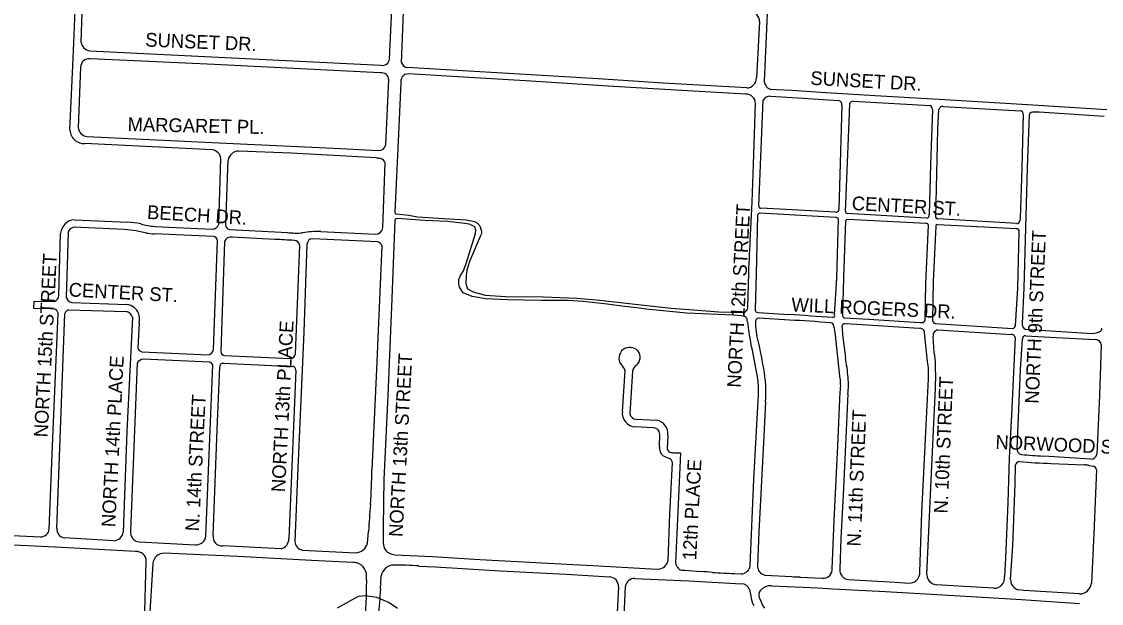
# Model space of a CAD drawing. Extents: x 0 to 712119, y 0 to 761125.
# Drawn here: x 682403 to 686331, y 737468 to 739583 of the extents above; entities that cross this region are included whole.
import ezdxf

# ---------------------------------------------------------------- set-up
doc = ezdxf.new("R2010")
doc.units = 0
for name, color, linetype in [('PAVED ROADS', 7, 'Continuous'), ('stream or creek', 7, 'Continuous'), ('street names', 7, 'Continuous')]:
    doc.layers.add(name, color=color, linetype=linetype)

msp = doc.modelspace()

# ---------------------------------------------------------------- linework, layer by layer
at = {"layer": 'PAVED ROADS'}
for points in [[(685104.8, 739365.5), (685126.5, 739832.4), (685138.5, 740091.5)], [(682578.5, 739189), (682590, 739449.5), (682599.5, 739683), (682609.6, 739931.8), (682635.8, 739930.4), (682631.1, 739819.2)], [(683785, 739433), (683793.5, 739649.5), (683799.8, 739773.9)], [(682626, 739724.5), (682618.7, 739510.1)], [(683741.5, 739447), (683751.5, 739682)], [(685087.6, 739583.4), (685076.4, 739378.9)], [(682650.6, 739476.9), (683710, 739424.5)], [(682616.5, 739417.5), (682608, 739198)], [(683707.5, 739397), (683417.8, 739411.3), (683104.5, 739427.5), (682652.5, 739448.5)], [(685040.6, 739342.1), (684737, 739359.5), (684500.5, 739375), (684255.5, 739390), (684029, 739403), (683805.5, 739416)], [(685038, 739319.5), (684846, 739330), (684556, 739347.5), (684236.5, 739367.5), (683929, 739386), (683811.5, 739393)], [(683728, 739136), (683739, 739372)], [(683782, 739361.5), (683774.5, 739173.5), (683761, 738890.5)], [(685127, 739312), (685246.5, 739305.5), (685375, 739297)], [(686351, 739262.5), (686062, 739281.2), (685760, 739299), (685507.5, 739313.5), (685328.5, 739324.5), (685204.5, 739332.5), (685150.3, 739335.5), (685131.1, 739336.7)], [(685060, 738928.5), (685065, 739063.5), (685072.5, 739286)], [(685085, 738913), (685100.5, 739297.5)], [(685386.5, 739278.5), (685376, 738901)], [(685400.5, 738892.5), (685413.5, 739220), (685416, 739286.5)], [(685427.5, 739293.5), (685707.5, 739278.5)], [(685716, 739264), (685709.5, 739062.5), (685704.5, 738882)], [(685728.5, 738871.5), (685736.2, 739191.3), (685739.3, 739264.4)], [(685755, 739275), (686037, 739259)], [(686046, 739248.5), (686041, 739050.5), (686035, 738868.5), (686034.5, 738859), (686034.5, 738859)], [(686068, 739244), (686061.3, 739051.8), (686048.5, 738613.5), (686043, 738486)], [(686341, 739238.5), (686104.8, 739254.4), (686086.5, 739254.5)], [(682640, 739165.5), (683147, 739141.5), (683563, 739121.5), (683700, 739114.5), (683700, 739114.5)], [(683097.6, 739116.7), (682633, 739139.5)], [(683692.5, 739087.5), (683383, 739105), (683192.5, 739112.5)], [(683120, 738846.5), (683128, 739086)], [(683153.6, 739080.1), (683144.7, 738845.2)], [(683717, 738835), (683726, 739069.5)], [(685054.3, 738805), (685060, 738928.5), (685060, 738928.5)], [(685035.8, 738509.3), (685031.5, 738510.4), (685020.5, 738513), (684993.5, 738515.5), (684823, 738522.5), (684686, 738536), (684639.5, 738543), (684586.5, 738548.5), (684533, 738556), (684446, 738565.5), (684391, 738569), (684293.5, 738569.5), (684172, 738571.5), (684091.5, 738575.5), (684042.5, 738583.5), (684009.5, 738596.5), (683995.5, 738617), (683993, 738630), (683993.5, 738645), (683999, 738660), (684010, 738677), (684020, 738704), (684054.5, 738813), (684055.5, 738825), (684051, 738837), (684032, 738846.5), (684004.5, 738850.5), (683953.5, 738857), (683871.5, 738860.5), (683852, 738861), (683802.5, 738865), (683770, 738867.5), (683765.5, 738866.5), (683762, 738864), (683761, 738861)], [(683765, 738884), (683811, 738879), (683843, 738873.5), (683939, 738867.5), (684020, 738862.5), (684050.5, 738856), (684061.5, 738850), (684066, 738845), (684071.5, 738836.5), (684075.5, 738821), (684075.5, 738812), (684071.5, 738802), (684032, 738711.5), (684023, 738679), (684019.5, 738658.5), (684019, 738631.5), (684024.5, 738612), (684045, 738600.5), (684089.5, 738589), (684163, 738583.5), (684300, 738582), (684423, 738578), (684506.5, 738570.5), (684624.5, 738557), (684765.5, 738541.5), (684846.5, 738535), (684939.5, 738528), (685026.5, 738525)], [(685079.6, 738878.3), (685075, 738667), (685071, 738538)], [(685364, 738871), (685089.5, 738887)], [(685364.5, 738890.5), (685092, 738905)], [(685695, 738869), (685406, 738885.5)], [(682775.7, 738827), (682594.5, 738836)], [(682595, 738863), (682789.8, 738853.8)], [(682888, 738838.5), (683096, 738828.5)], [(683160.6, 738827), (683369.5, 738815.9)], [(683761, 738861), (683750, 738576.5), (683735, 738223.5), (683720.9, 737918.7), (683719.6, 737834.3)], [(685360.5, 738517), (685368.5, 738649.9), (685375, 738865)], [(685400.5, 738858.5), (685392.5, 738653), (685389, 738518)], [(685692.7, 738848.9), (685408, 738864)], [(685689.3, 738498.4), (685691.7, 738631.4), (685702, 738841.8)], [(685728.5, 738839.5), (685719.5, 738639), (685717, 738496.5)], [(686023, 738849), (685734.5, 738865.5)], [(686021.5, 738829.5), (685856.6, 738838.8), (685734.5, 738844.5)], [(682538, 738587), (682544.5, 738814)], [(682571.8, 738815.9), (682565.5, 738580.5)], [(682857.4, 738814.5), (682820, 738822.3)], [(683100.5, 738801.5), (682886.7, 738811.8)], [(683324.5, 738791), (683168.5, 738800)], [(683699, 738782), (683460.5, 738793.7)], [(683491, 738820), (683689.5, 738810)], [(683491, 738820), (683491, 738820)], [(686018.5, 738478), (686027, 738613), (686032, 738819.5)], [(683101, 738390.5), (683116, 738786.5)], [(683141.5, 738783.4), (683127, 738383)], [(683440.7, 738772.8), (683438.5, 738703), (683429, 738455.6), (683406.4, 737931.3), (683397, 737692)], [(683399, 738375.5), (683415.5, 738769.5)], [(683677.5, 737953.5), (683695, 738319.5), (683714, 738768)], [(685044.5, 738542), (685047.9, 738669.5)], [(682520.4, 738538.7), (682447.5, 738540.5), (682448.5, 738566.5), (682522, 738565.5)], [(682585, 738562), (682786, 738554.5)], [(682503.5, 737738), (682516.5, 738069.5), (682535.5, 738522.5)], [(682531.5, 737739.5), (682560.5, 738522)], [(682573.9, 738535.5), (682782.6, 738528.6)], [(685082.5, 738526), (685193.8, 738517.8)], [(682806, 738509), (682786.2, 738093.1), (682772.5, 737727)], [(682830.5, 738488), (682826, 738395.9)], [(685043.5, 738490.3), (685042.9, 738498.5)], [(685196.5, 738497.5), (685086, 738504.5)], [(685397, 738506.5), (685485, 738501.5), (685668.8, 738489)], [(685668, 738467.5), (685461, 738481), (685398.5, 738484.5)], [(685727.5, 738485), (686008, 738467.5)], [(685379.9, 738294.3), (685363.5, 738443)], [(685387.5, 738471), (685389.7, 738443.9), (685399.6, 738361.5)], [(685698.6, 738347.5), (685687.5, 738452.5)], [(685723, 738380), (685719, 738438.5)], [(685736.5, 738462), (686002.5, 738446)], [(686017, 738434), (686012.5, 738332.5), (686003.7, 738153.7), (685995.9, 737995.9), (685990.6, 737832.9), (685982, 737633), (685978.5, 737565)], [(686054, 738465), (686297.5, 738449.5)], [(686055.5, 738441), (686166, 738435), (686311, 738427)], [(686024.5, 738030.5), (686036.5, 738318), (686043.5, 738428)], [(686330.5, 738407.5), (686324, 738223.5), (686313.9, 738010.8)], [(682840, 738383), (683082.5, 738372)], [(683086.5, 738344.5), (682845, 738355.5)], [(683140.5, 738368.5), (683380, 738358)], [(682823.6, 738341.5), (682799.5, 737731.5)], [(683072.5, 737712), (683098.5, 738335.5)], [(683099.5, 737714.5), (683114.8, 738099.6), (683123.7, 738327.2)], [(683136, 738341.5), (683388.1, 738329.3)], [(683400, 738316), (683375, 737702.5)], [(684588.8, 738165.8), (684598.5, 738313.5)], [(684625.5, 738312.5), (684616, 738158)], [(685671, 737582.5), (685678.3, 737797.9), (685689.4, 738041.4), (685701.5, 738284.7)], [(685696.5, 737572.5), (685712.5, 737941.4), (685727.1, 738250.4)], [(685053, 737605.5), (685066.8, 737918.1), (685082, 738206)], [(685108.6, 738200.2), (685102.3, 738051.3), (685085.3, 737727.2), (685080, 737604.5)], [(685352, 737594), (685359.3, 737767.6), (685372.4, 738040.7), (685381, 738236.9)], [(685408.9, 738229.1), (685400.6, 738042.4), (685392, 737862), (685383, 737703), (685379, 737591.5)], [(684639, 738137.5), (684713, 738133.5)], [(684700, 738106.5), (684635, 738110)], [(684723, 738038.5), (684724.4, 738082.9)], [(684753.5, 738079.5), (684751.4, 738029.9)], [(684777.4, 738015.5), (684800, 738014.5), (684781.5, 737615.5)], [(686293, 737992.5), (686120, 738003.5)], [(684754.5, 737623.5), (684760.9, 737793.3), (684771, 737979)], [(686000.5, 737554), (686008.2, 737676.5), (686017, 737903.4), (686018.2, 737971.8)], [(686147.8, 737976.4), (686270, 737971.2)], [(686287, 737969.5), (686302, 737966.5)], [(686313, 737953), (686303, 737722), (686294.5, 737540.5)], [(682817.5, 737656.5), (682524.5, 737672), (682220.5, 737686), (681850.5, 737704.5), (681462.5, 737723.5), (681253.5, 737733.5), (681253.5, 737733.5)], [(682062, 737729.5), (682472, 737709.5)], [(683661.5, 737686.5), (683665, 737729)], [(682738, 737695.5), (682558.5, 737706.5)], [(682830.5, 737691.5), (683036, 737681)], [(683072.5, 737712), (683072.5, 737712)], [(683718.5, 737688), (683720.5, 737675)], [(683609, 737616.5), (683558, 737619), (683457, 737624), (683189.5, 737638), (682948.5, 737649), (682921.5, 737650)], [(683347, 737666), (683134.5, 737676.5)], [(683424, 737661.5), (683618.5, 737651.5)], [(682849.9, 737393.6), (682856.5, 737621)], [(682880.5, 737612.5), (682866.5, 737397)], [(683639.5, 737606.5), (683631, 737611.5)], [(683761, 737644.5), (683897.5, 737637.5), (684070, 737627.5), (684409, 737608.5), (684481, 737605), (684693, 737593.5), (684720, 737592)], [(683658, 737552), (683657, 737577)], [(683847.5, 737603.5), (683908, 737600.5), (684144, 737586.5), (684384, 737573.5), (684541, 737564)], [(684805, 737588.5), (684815.5, 737588), (684874, 737583)], [(684995.5, 737576), (685021, 737574.5)], [(685107, 737570.5), (685204.5, 737565)], [(683709, 737519.5), (683711, 737568)], [(684634, 737558), (684830.5, 737549.5), (685021.5, 737538.5)], [(685131, 737531.5), (685244.5, 737527), (685299.5, 737524), (685353, 737521), (685545, 737511), (685816, 737495.5), (686040.5, 737482), (686251, 737467.5)], [(685234.5, 737563.5), (685315, 737559)], [(685410.5, 737554), (685580.5, 737544.5), (685632, 737541)], [(685656.5, 737549.5), (685656.5, 737549.5)], [(685940, 737522.5), (685831.5, 737529.5), (685731, 737535.5)], [(684574.5, 737528), (684564.5, 737341.5), (684558, 737198.5)], [(684578, 737015), (684584.7, 737163.1), (684593.2, 737392.9), (684600, 737530)], [(685050.5, 737518), (685055.5, 737494.5)], [(685086, 737505.5), (685091.5, 737515.5)], [(686251.5, 737502), (686048.5, 737515), (686030.5, 737516.5)], [(683655, 737435.5), (683656.5, 737479)]]:
    msp.add_lwpolyline(points, dxfattribs=at)
for centre, radius, start, end in [((685050.7, 739583.2), 37, 0.3484, 88.118), ((682657.3, 739515.3), 38.9, 187.6834, 260.1372), ((682650, 739415), 33.6, 85.7729, 175.6913), ((683715, 739450.8), 26.8, 259.2972, 351.7782), ((683809.7, 739441.9), 26.2, 199.8342, 260.8301), ((683711.2, 739369.3), 27.9, 5.5467, 97.5787), ((683820.1, 739363.4), 38.1, 151.713, 182.9262), ((683809.2, 739365.1), 28, 85.2468, 144.158), ((685039.1, 739379.3), 37.2, 272.2318, 359.3414), ((685135.9, 739367.5), 31.2, 183.6873, 261.0802), ((685038.5, 739285.5), 34, 0.8274, 90.8576), ((685125, 739284.2), 27.9, 85.916, 151.4563), ((685127, 739312), 0.000000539, 160.6959, 251.9189), ((685371.1, 739281.7), 15.8, 348.1161, 75.6158), ((685426.5, 739282.2), 11.3, 84.9199, 157.7375), ((685702.7, 739266), 13.4, 351.5932, 69.1651), ((685753.7, 739260), 15, 85.0408, 163.3086), ((685755, 739275), 0.0000024, 145.7508, 225.4512), ((686036, 739249), 10, 356.9208, 84.2818), ((686083.9, 739237.5), 17.2, 81.3064, 157.8493), ((682631.6, 739191.7), 53.1, 182.8973, 230.8265), ((682646.6, 739204), 39, 188.8069, 260.3048), ((682635.1, 739207.5), 68, 236.9073, 268.1983), ((683091.5, 739080.3), 37, 8.9386, 80.4579), ((683194, 739071.2), 41.3, 92.0455, 167.6256), ((683701.8, 739141.1), 26.7, 266.0452, 348.993), ((683676.6, 738939.6), 148.8, 77.8126, 83.8627), ((683704.5, 739062.7), 22.5, 17.4726, 81.0632), ((685091.6, 738911.7), 6.73, 169.0609, 273.3109), ((683766, 738889.1), 5.15, 163.838, 259.377), ((685090.4, 738876.1), 10.9, 94.4831, 168.083), ((685364.5, 738858.8), 12.2, 30.4691, 92.31), ((685366.3, 738900.1), 9.74, 259.343, 5.4519), ((685406.3, 738891.4), 5.91, 169.2645, 267.0499), ((685695, 738878.9), 9.94, 269.7699, 17.9138), ((685735.5, 738872.5), 7.07, 188.1301, 261.8699), ((682598.7, 738808.7), 54.4, 93.8628, 174.4098), ((682596.7, 738810.7), 25.3, 94.8838, 168.3688), ((682757.1, 738434.7), 392.7, 80.7809, 87.2838), ((682788, 738661.8), 192, 75.5179, 89.4728), ((682904.5, 739083.9), 246, 253.8415, 266.1634), ((683096.5, 738852.9), 24.4, 268.8584, 344.8814), ((683163.5, 738845.5), 18.8, 180.842, 261.0883), ((683688.7, 738838.5), 28.5, 271.612, 352.9354), ((685407.8, 738856.5), 7.54, 88.1651, 164.3426), ((685694.7, 738841.8), 7.34, 0.1536, 105.2221), ((685732.6, 738840.7), 4.27, 63.7583, 195.8528), ((686023.4, 738820.9), 8.76, 350.5346, 102.2598), ((686024.1, 738859.3), 10.4, 263.6477, 358.3705), ((682891.1, 739020.5), 208.7, 260.7145, 268.7912), ((683100, 738785.5), 16, 3.6135, 88.2649), ((683165.2, 738775.1), 25.1, 82.3951, 160.8227), ((683249.8, 736574.5), 2217.8, 86.246, 88.0697), ((683403.9, 739246.6), 432.1, 265.4259, 272.7939), ((683393.2, 738764.8), 22.8, 11.8761, 85.5545), ((683483.8, 738477.5), 342.6, 88.789, 99.8756), ((683462.7, 738771.8), 22.1, 95.695, 177.416), ((654252.7, 740183.1), 30832.4, 357.18619, 357.43837), ((683694.7, 738762.3), 20.1, 16.3489, 77.601), ((682516, 738586.6), 22, 285.7578, 0.9299), ((682588.4, 738585.1), 23.4, 191.4055, 261.6093), ((682778, 738499.8), 55.3, 22.5279, 81.6299), ((682515.5, 738519), 20.3, 10.031, 76.0145), ((682580.5, 738515.5), 21, 108.0951, 161.9259), ((682779.2, 738500.8), 28, 17.0241, 83.0613), ((682726.5, 738499.8), 104.7, 353.5262, 11.6789), ((685027.8, 738536.2), 11.3, 263.6598, 316.7899), ((685022.2, 738546.6), 22.8, 307.2968, 348.3117), ((685088, 738537.2), 17, 177.2058, 212.2212), ((685080.4, 738536.9), 11.1, 232.3474, 280.9435), ((682955.8, 702333.6), 36253.3, 86.20711, 86.46085), ((685355.1, 738513.8), 6.34, 260.4248, 30.8145), ((685397, 738515), 8.52, 159.5512, 270.0978), ((685030.2, 738498), 12.7, 2.4531, 63.5709), ((685657.1, 738549), 616.3, 185.4685, 192.6193), ((685085.4, 738491.4), 13.1, 87.3989, 190.4915), ((685255.8, 738486.7), 183.3, 179.284, 193.9945), ((685085.7, 735718.7), 2781, 84.6295, 87.7169), ((685344.3, 738473.7), 13.9, 9.5205, 82.9173), ((684941.5, 738389.6), 425.4, 7.2086, 11.7161), ((685397.2, 738474.3), 10.3, 82.6853, 198.9674), ((685671, 738654.5), 165.6, 269.2565, 272.9263), ((685680.5, 738498), 8.87, 263.1735, 3.0253), ((685728.1, 738496.1), 11.1, 177.9704, 266.8245), ((686007.5, 738478.5), 11, 272.6026, 357.3974), ((686061.3, 738482.2), 18.7, 168.3187, 246.9733), ((683024.8, 737962.4), 2108.5, 9.8217, 13.1584), ((685671.6, 738452), 15.9, 1.6267, 103.2361), ((685738.9, 738441.9), 20.2, 96.8815, 189.7698), ((686004, 738433), 13, 4.207, 96.5716), ((686054.7, 738429.7), 11.3, 85.7477, 188.8335), ((686055.5, 738441), 0.0000011, 90.4789, 137.5539), ((686299.6, 738501), 51.5, 267.6321, 303.2299), ((686320.3, 738467.5), 12.3, 307.9499, 6.8205), ((682841.7, 738398.9), 16, 190.8978, 263.8508), ((684614.9, 738358), 40.8, 42.4281, 125.9406), ((682004.4, 737746.9), 3123.4, 10.396, 12.3396), ((686310.4, 738406.9), 20.1, 1.6462, 88.3538), ((682846.4, 738330), 25.6, 93.0826, 153.1567), ((683077.1, 738395.9), 24.5, 282.7472, 347.2528), ((683144.1, 738385.4), 17.3, 187.9264, 257.9827), ((683378.3, 738378.9), 21, 274.6751, 350.6183), ((684616.2, 738359.6), 40.3, 128.6615, 215.8082), ((684616.5, 738362.3), 36.7, 306.4283, 39.1639), ((684773.8, 738238.6), 637.7, 4.4936, 11.1123), ((685488.3, 738334.8), 239, 359.7734, 10.902), ((683085.1, 738330.1), 14.4, 21.8014, 84.4588), ((683135.4, 738329.6), 11.9, 86.9956, 191.3745), ((683136, 738341.5), 0.000000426, 311.2876, 57.296), ((683388.7, 738317.9), 11.5, 350.6034, 93.0524), ((684555.3, 738301), 45, 16.1929, 51.1873), ((684653.4, 738309), 28.1, 122.3535, 172.9097), ((684668.5, 738238.7), 441.8, 354.9951, 10.8698), ((685440.8, 738304.2), 261.4, 355.7243, 9.5456), ((684894.5, 738294.2), 833.7, 356.9901, 2.7288), ((684762.2, 738241.6), 321.7, 353.6536, 12.372), ((685171.5, 738261.5), 211, 353.3156, 8.9425), ((685078, 738262.5), 332.7, 354.2325, 4.4917), ((684636, 738157.8), 47.9, 170.4501, 268.8574), ((684638.7, 738160.4), 22.9, 185.9192, 270.6592), ((684704.1, 738084.6), 49.7, 354.0951, 79.6447), ((684699.8, 738081.9), 24.6, 2.2529, 89.6498), ((684760.9, 738033.4), 38.2, 172.382, 230.3592), ((685141.8, 738904.8), 987.8, 245.774, 247.2288), ((684766.7, 738032.2), 15.5, 188.4702, 249.6084), ((684775, 738057.7), 42.3, 251.1277, 273.2613), ((686043.7, 738028), 19.4, 172.624, 258.954), ((686176.5, 739410.3), 1407.9, 264.4352, 267.699), ((686293.4, 738013.2), 20.7, 268.8934, 353.3765), ((684753.9, 737977.8), 17.1, 3.9847, 70.9676), ((686033.5, 737966.9), 16.1, 91.8084, 162.5172), ((686228, 740387.8), 2412.7, 265.3634, 268.0935), ((686265.9, 737847), 124.3, 80.24, 88.1193), ((686297.4, 737951.5), 15.7, 5.399, 72.9483), ((680861, 738013.3), 2817.1, 356.2179, 358.7832), ((686282.4, 737592.5), 2621, 174.8557, 177.0145), ((688622, 737725.1), 4903.6, 178.7235, 180.4332), ((682471.8, 737741.4), 31.9, 270.361, 353.9142), ((682561.3, 737736.3), 29.9, 173.9049, 264.6739), ((682531.5, 737739.5), 0.000000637, 261.2053, 338.763), ((682736.5, 737731.8), 36.4, 272.4375, 352.3574), ((682833.2, 737725.6), 34.2, 170.0191, 265.5322), ((683039.2, 737714.2), 33.3, 264.4129, 356.2706), ((683132.4, 737709.7), 33.3, 171.7406, 273.5528), ((683338.1, 737701.8), 36.9, 283.9379, 1.0768), ((683430.1, 737694.1), 33.2, 183.6607, 259.3728), ((682819.7, 737619.7), 36.8, 1.9953, 93.3842), ((682921, 737609.4), 40.6, 89.2991, 175.5951), ((683615.6, 737699), 47.6, 273.547, 344.741), ((683758, 737685.2), 38.9, 195.2193, 244.8413), ((683771.9, 737720.5), 76.8, 246.6688, 261.8288), ((683603.9, 737548.5), 68.2, 77.2171, 85.7213), ((683612.8, 737571.4), 44.1, 65.5888, 81.8908), ((684716.1, 737630.9), 39.1, 275.6984, 349.0965), ((684809.7, 737618.4), 28.4, 185.8597, 225.9533), ((683602.4, 737564.6), 56, 12.8277, 48.5269), ((683758.8, 737558.3), 48.8, 92.6932, 168.5094), ((683742.9, 736068.5), 1538.6, 86.1015, 89.4933), ((684806.2, 737607), 18.6, 209.107, 266.1981), ((684858.2, 737065.8), 517.4, 83.5824, 88.2464), ((686011.4, 758559.4), 21008, 267.01107, 267.22817), ((685018.6, 737609), 34.6, 273.9712, 354.21), ((685113.8, 737603.6), 33.8, 178.4769, 258.4305), ((685319.6, 737591.6), 32.5, 316.0801, 4.3221), ((685415.3, 737590), 36.4, 177.6106, 221.2695), ((685628.8, 737581.4), 42.2, 311.0293, 1.5299), ((685732.3, 737571.5), 35.8, 178.3439, 238.366), ((684370, 737500.9), 713.9, 175.8914, 181.7543), ((684540, 737529.5), 34.5, 357.5305, 88.3493), ((684632.4, 737525.3), 32.8, 87.2551, 171.6898), ((685022, 737508.4), 30.1, 18.5979, 90.8894), ((685127.2, 737484.1), 47.6, 85.4347, 138.6674), ((685246.9, 738111.6), 548.2, 265.5678, 268.7074), ((685318.9, 737592.3), 33.6, 263.3642, 315.9434), ((685414.4, 737588.4), 34.6, 220.3302, 263.5248), ((685629, 737589.3), 48.4, 273.5824, 304.6849), ((685733.5, 737574.1), 38.7, 238.8459, 266.2598), ((685940.9, 737560.4), 37.9, 268.6555, 6.9987), ((686039, 737554.1), 38.5, 180.1287, 257.1909), ((686251.6, 737545.1), 43.1, 269.8132, 353.8661), ((689320.5, 736952.3), 5640.1, 174.2288, 175.2235), ((685160.4, 737507.4), 105.7, 187.0193, 206.7728), ((685110.2, 737496.9), 25.6, 160.4115, 210.2176), ((685284.1, 737560.3), 210.4, 201.2512, 211.7403)]:
    msp.add_arc(centre, radius, start, end, dxfattribs=at)
at = {"layer": 'stream or creek'}
msp.add_lwpolyline([(683552.5, 737451.2), (683628, 737493.7), (683654.7, 737496.2), (683693.4, 737490.6), (683740.4, 737470.9), (683770.3, 737450.6)], dxfattribs=at)

# ---------------------------------------------------------------- texts
at = {"layer": 'street names'}
for s, rotation, p in [('SUNSET DR.', 357.6163, (682852, 739493)), ('SUNSET DR.', 356.8563, (685271.4, 739353.7)), ('MARGARET PL.', 358.7249, (682788.1, 739185.5)), ('CENTER ST.', 356.8752, (685421.8, 738898.4)), ('BEECH DR.', 356.5566, (682858.2, 738866.2)), ('NORTH 12th STREET', 87.0109, (685019, 738251.1)), ('NORTH 9th STREET', 87.5807, (686102.9, 738193)), ('NORTH 15th STREET', 87.1175, (682497.5, 738070.5)), ('CENTER ST.', 356.9051, (682573.2, 738584.2)), ('WILL ROGERS DR.', 357.4321, (685202.2, 738529.6)), ('NORTH 13th PLACE', 87.1175, (683361.1, 737871.2)), ('NORTH 14th PLACE', 87.1175, (682743.4, 737743.9)), ('NORTH 13th STREET', 86.9341, (683788.5, 737708.1)), ('N. 10th STREET', 87.6367, (685771.2, 737793.8)), ('N. 14th STREET', 87.1175, (683047.9, 737728.8)), ('N. 11th STREET', 87.6094, (685455.1, 737673.8)), ('NORWOOD ST.', 357.5088, (685944.9, 738029.9)), ('12th PLACE', 86.9779, (684856.8, 737623.5))]:
    msp.add_text(s, height=50, rotation=rotation, dxfattribs=at).set_placement(p)

doc.saveas('drawing.dxf')
